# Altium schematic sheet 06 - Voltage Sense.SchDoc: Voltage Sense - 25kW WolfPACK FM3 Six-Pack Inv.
size 431 x 279 mm; Date: 09/2024; DocumentNumber: CRD25DA12N-FMC; Revision: 2.0; SheetNumber: 6; SheetTotal: 9; SheetSize: B
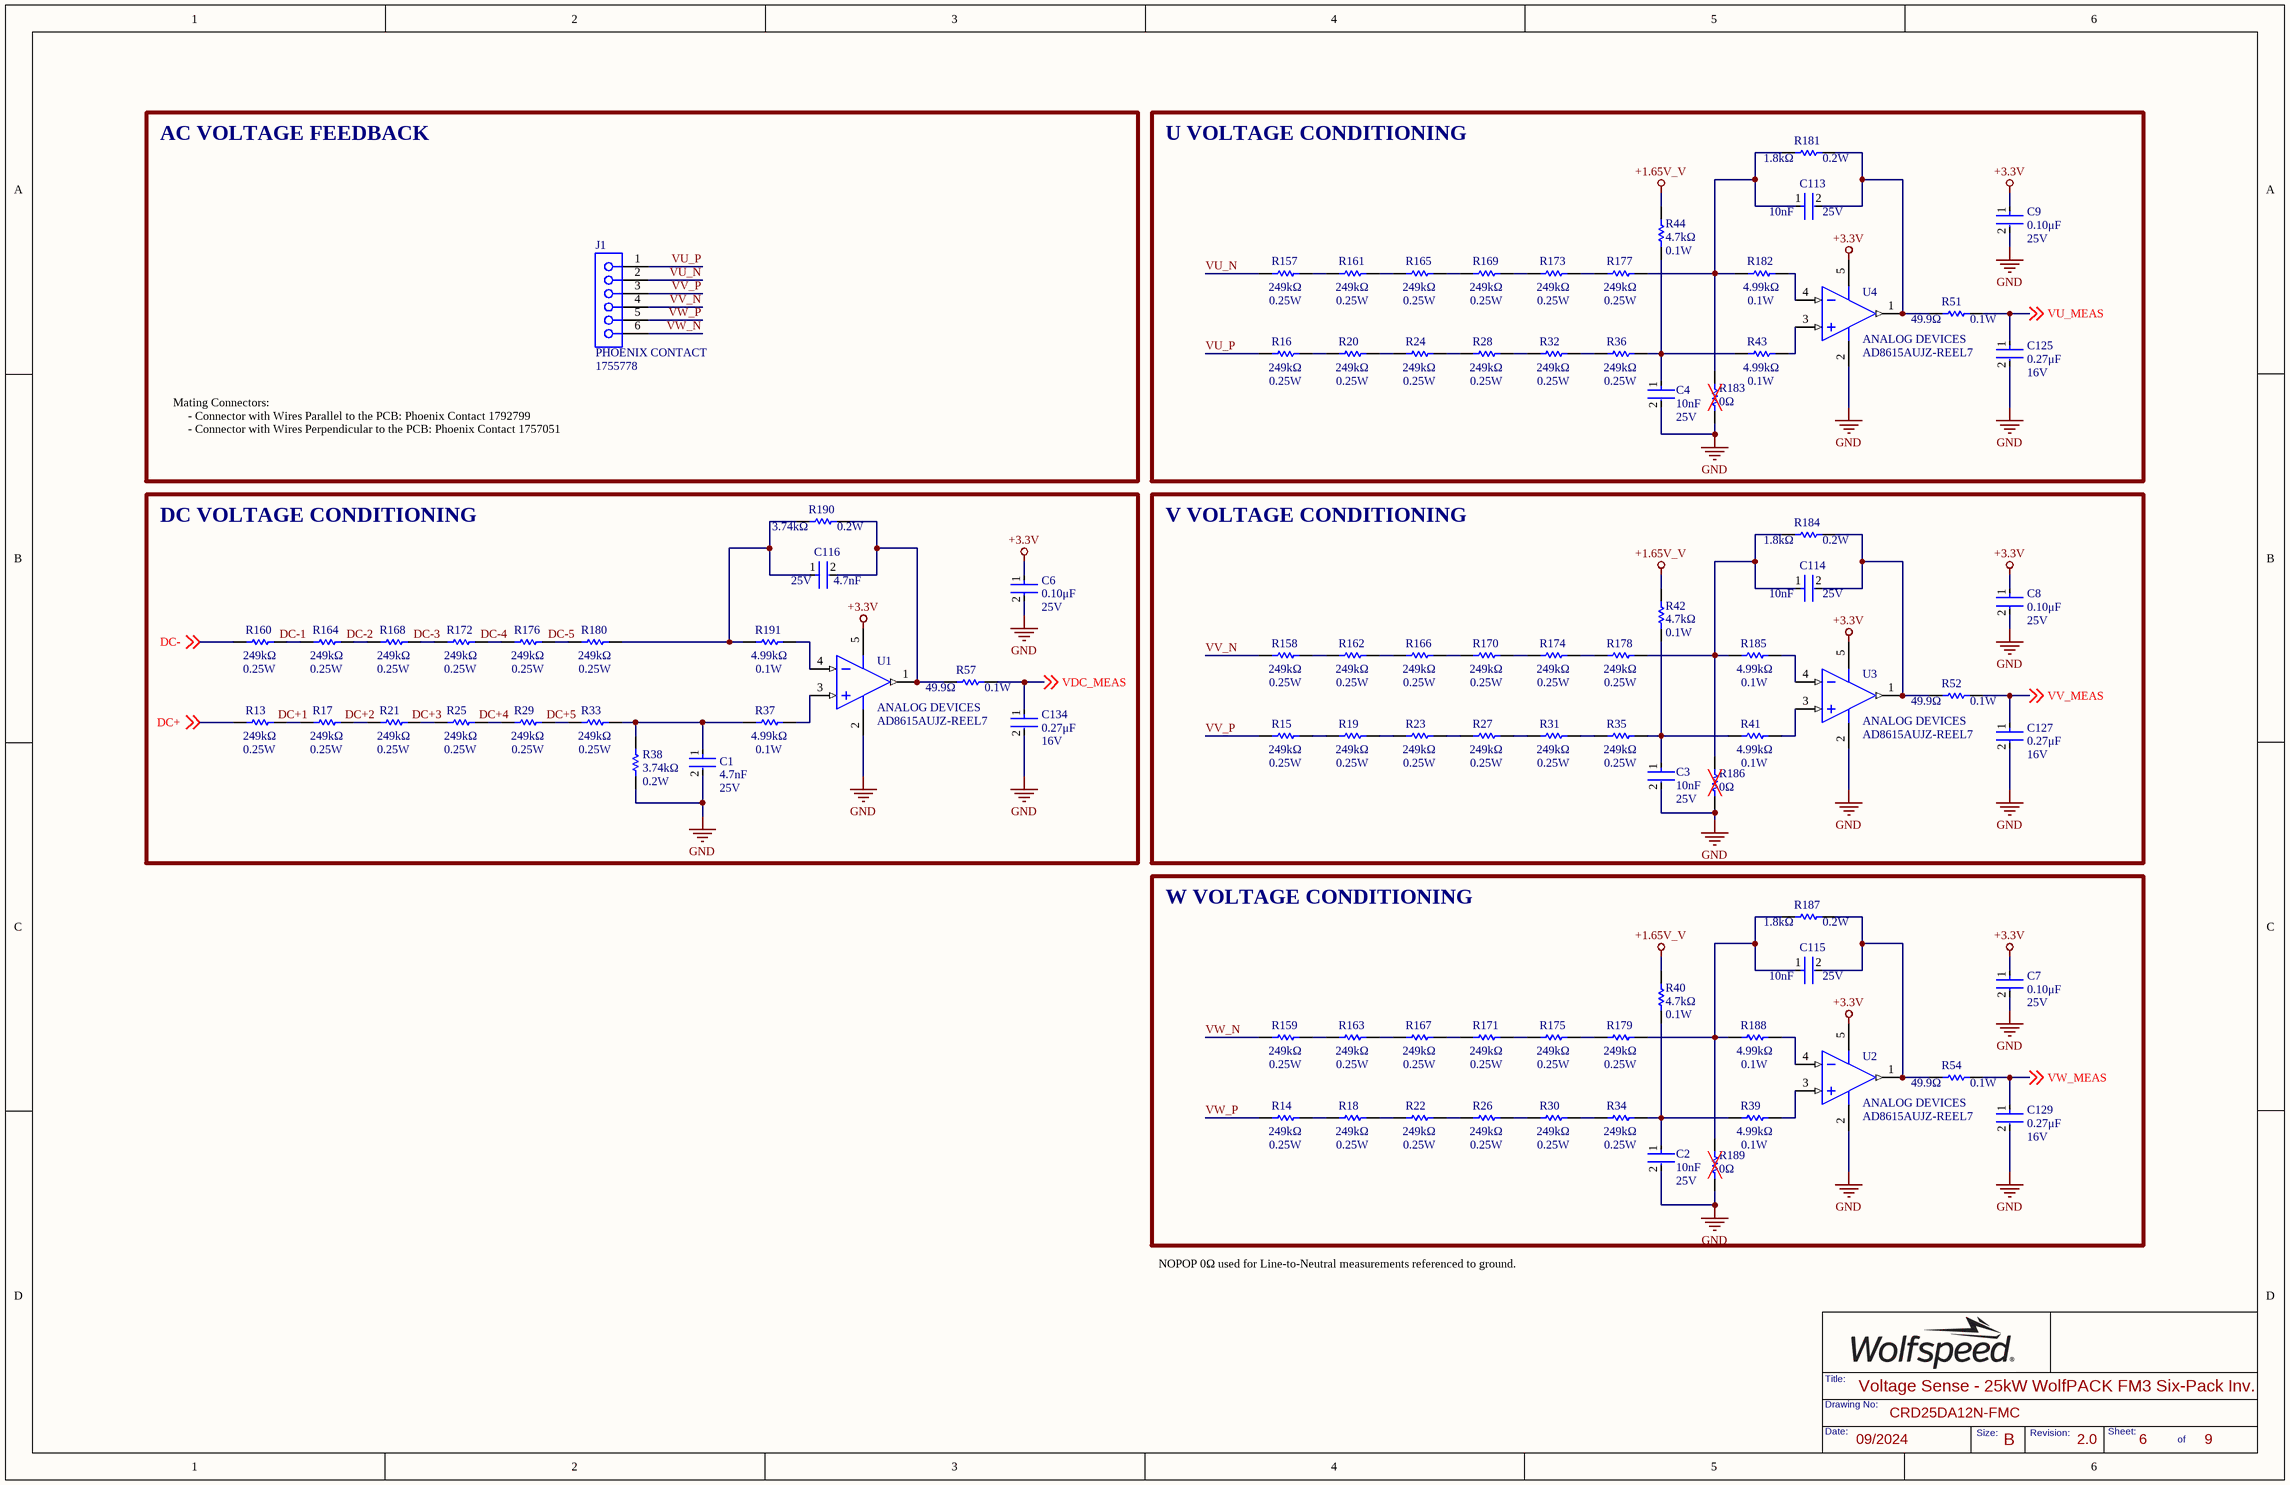
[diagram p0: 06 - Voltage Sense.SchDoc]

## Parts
C1  Voltage Rating: 25V  Capacitance: 4.7nF  [FP-C0603C-CF-IPC_B]  (hidden comment: C0603C472K3RAC7867)
C2  value 10nF  Voltage Rating: 25V  [FP-C0603C-CF-IPC_B]  (hidden comment: CL10B103KA8WPNC)
C3  value 10nF  Voltage Rating: 25V  [FP-C0603C-CF-IPC_B]  (hidden comment: CL10B103KA8WPNC)
C4  value 10nF  Voltage Rating: 25V  [FP-C0603C-CF-IPC_B]  (hidden comment: CL10B103KA8WPNC)
C6  Voltage Rating: 25V  Capacitance: 0.10μF  [FP-C0603C-CF-IPC_B]  (hidden comment: C0603C104K3RACTU)
C7  Voltage Rating: 25V  Capacitance: 0.10μF  [FP-C0603C-CF-IPC_B]  (hidden comment: C0603C104K3RACTU)
C8  Voltage Rating: 25V  Capacitance: 0.10μF  [FP-C0603C-CF-IPC_B]  (hidden comment: C0603C104K3RACTU)
C9  Voltage Rating: 25V  Capacitance: 0.10μF  [FP-C0603C-CF-IPC_B]  (hidden comment: C0603C104K3RACTU)
C113  value 10nF  Voltage Rating: 25V  [FP-C0603C-CF-IPC_B]  (hidden comment: CL10B103KA8WPNC)
C114  value 10nF  Voltage Rating: 25V  [FP-C0603C-CF-IPC_B]  (hidden comment: CL10B103KA8WPNC)
C115  value 10nF  Voltage Rating: 25V  [FP-C0603C-CF-IPC_B]  (hidden comment: CL10B103KA8WPNC)
C116  Voltage Rating: 25V  Capacitance: 4.7nF  [FP-C0603C-CF-IPC_B]  (hidden comment: C0603C472K3RAC7867)
C125  Voltage Rating (DC): 16V  Capacitance: 0.27μF  [FP-GCM188-0_1-IPC_A]  (hidden comment: GCM188R71C274KA37D)
C127  Voltage Rating (DC): 16V  Capacitance: 0.27μF  [FP-GCM188-0_1-IPC_A]  (hidden comment: GCM188R71C274KA37D)
C129  Voltage Rating (DC): 16V  Capacitance: 0.27μF  [FP-GCM188-0_1-IPC_A]  (hidden comment: GCM188R71C274KA37D)
C134  Voltage Rating (DC): 16V  Capacitance: 0.27μF  [FP-GCM188-0_1-IPC_A]  (hidden comment: GCM188R71C274KA37D)
J1  1755778  Manufacturer Print: PHOENIX CONTACT  [1755778]
R13  Resistance: 249kΩ  Power: 0.25W  [RESC3216X65X50NL15T25]  (hidden comment: TNPW1206249KBEEA)
R14  Resistance: 249kΩ  Power: 0.25W  [RESC3216X65X50NL15T25]  (hidden comment: TNPW1206249KBEEA)
R15  Resistance: 249kΩ  Power: 0.25W  [RESC3216X65X50NL15T25]  (hidden comment: TNPW1206249KBEEA)
R16  Resistance: 249kΩ  Power: 0.25W  [RESC3216X65X50NL15T25]  (hidden comment: TNPW1206249KBEEA)
R17  Resistance: 249kΩ  Power: 0.25W  [RESC3216X65X50NL15T25]  (hidden comment: TNPW1206249KBEEA)
R18  Resistance: 249kΩ  Power: 0.25W  [RESC3216X65X50NL15T25]  (hidden comment: TNPW1206249KBEEA)
R19  Resistance: 249kΩ  Power: 0.25W  [RESC3216X65X50NL15T25]  (hidden comment: TNPW1206249KBEEA)
R20  Resistance: 249kΩ  Power: 0.25W  [RESC3216X65X50NL15T25]  (hidden comment: TNPW1206249KBEEA)
R21  Resistance: 249kΩ  Power: 0.25W  [RESC3216X65X50NL15T25]  (hidden comment: TNPW1206249KBEEA)
R22  Resistance: 249kΩ  Power: 0.25W  [RESC3216X65X50NL15T25]  (hidden comment: TNPW1206249KBEEA)
R23  Resistance: 249kΩ  Power: 0.25W  [RESC3216X65X50NL15T25]  (hidden comment: TNPW1206249KBEEA)
R24  Resistance: 249kΩ  Power: 0.25W  [RESC3216X65X50NL15T25]  (hidden comment: TNPW1206249KBEEA)
R25  Resistance: 249kΩ  Power: 0.25W  [RESC3216X65X50NL15T25]  (hidden comment: TNPW1206249KBEEA)
R26  Resistance: 249kΩ  Power: 0.25W  [RESC3216X65X50NL15T25]  (hidden comment: TNPW1206249KBEEA)
R27  Resistance: 249kΩ  Power: 0.25W  [RESC3216X65X50NL15T25]  (hidden comment: TNPW1206249KBEEA)
R28  Resistance: 249kΩ  Power: 0.25W  [RESC3216X65X50NL15T25]  (hidden comment: TNPW1206249KBEEA)
R29  Resistance: 249kΩ  Power: 0.25W  [RESC3216X65X50NL15T25]  (hidden comment: TNPW1206249KBEEA)
R30  Resistance: 249kΩ  Power: 0.25W  [RESC3216X65X50NL15T25]  (hidden comment: TNPW1206249KBEEA)
R31  Resistance: 249kΩ  Power: 0.25W  [RESC3216X65X50NL15T25]  (hidden comment: TNPW1206249KBEEA)
R32  Resistance: 249kΩ  Power: 0.25W  [RESC3216X65X50NL15T25]  (hidden comment: TNPW1206249KBEEA)
R33  Resistance: 249kΩ  Power: 0.25W  [RESC3216X65X50NL15T25]  (hidden comment: TNPW1206249KBEEA)
R34  Resistance: 249kΩ  Power: 0.25W  [RESC3216X65X50NL15T25]  (hidden comment: TNPW1206249KBEEA)
R35  Resistance: 249kΩ  Power: 0.25W  [RESC3216X65X50NL15T25]  (hidden comment: TNPW1206249KBEEA)
R36  Resistance: 249kΩ  Power: 0.25W  [RESC3216X65X50NL15T25]  (hidden comment: TNPW1206249KBEEA)
R37  Power Rating: 0.1W  Resistance: 4.99kΩ  [FP-MCR03-IPC_B]  (hidden comment: RC0603FR-074K99L)
R38  Max Power Dissipation: 0.2W  Resistance: 3.74kΩ  [FP-MCR03-IPC_B]  (hidden comment: ERJ-PB3B3741V)
R39  Power Rating: 0.1W  Resistance: 4.99kΩ  [FP-MCR03-IPC_B]  (hidden comment: RC0603FR-074K99L)
R40  Resistance: 4.7kΩ  Power Rating: 0.1W  [FP-MCR03-IPC_B]  (hidden comment: CRCW06034K70FKTA)
R41  Power Rating: 0.1W  Resistance: 4.99kΩ  [FP-MCR03-IPC_B]  (hidden comment: RC0603FR-074K99L)
R42  Resistance: 4.7kΩ  Power Rating: 0.1W  [FP-MCR03-IPC_B]  (hidden comment: CRCW06034K70FKTA)
R43  Power Rating: 0.1W  Resistance: 4.99kΩ  [FP-MCR03-IPC_B]  (hidden comment: RC0603FR-074K99L)
R44  Resistance: 4.7kΩ  Power Rating: 0.1W  [FP-MCR03-IPC_B]  (hidden comment: CRCW06034K70FKTA)
R51  Resistance: 49.9Ω  Power Rating: 0.1W  [FP-MCR03-IPC_B]  (hidden comment: ERJ-3EKF49R9V)
R52  Resistance: 49.9Ω  Power Rating: 0.1W  [FP-MCR03-IPC_B]  (hidden comment: ERJ-3EKF49R9V)
R54  Resistance: 49.9Ω  Power Rating: 0.1W  [FP-MCR03-IPC_B]  (hidden comment: ERJ-3EKF49R9V)
R57  Resistance: 49.9Ω  Power Rating: 0.1W  [FP-MCR03-IPC_B]  (hidden comment: ERJ-3EKF49R9V)
R157  Resistance: 249kΩ  Power: 0.25W  [RESC3216X65X50NL15T25]  (hidden comment: TNPW1206249KBEEA)
R158  Resistance: 249kΩ  Power: 0.25W  [RESC3216X65X50NL15T25]  (hidden comment: TNPW1206249KBEEA)
R159  Resistance: 249kΩ  Power: 0.25W  [RESC3216X65X50NL15T25]  (hidden comment: TNPW1206249KBEEA)
R160  Resistance: 249kΩ  Power: 0.25W  [RESC3216X65X50NL15T25]  (hidden comment: TNPW1206249KBEEA)
R161  Resistance: 249kΩ  Power: 0.25W  [RESC3216X65X50NL15T25]  (hidden comment: TNPW1206249KBEEA)
R162  Resistance: 249kΩ  Power: 0.25W  [RESC3216X65X50NL15T25]  (hidden comment: TNPW1206249KBEEA)
R163  Resistance: 249kΩ  Power: 0.25W  [RESC3216X65X50NL15T25]  (hidden comment: TNPW1206249KBEEA)
R164  Resistance: 249kΩ  Power: 0.25W  [RESC3216X65X50NL15T25]  (hidden comment: TNPW1206249KBEEA)
R165  Resistance: 249kΩ  Power: 0.25W  [RESC3216X65X50NL15T25]  (hidden comment: TNPW1206249KBEEA)
R166  Resistance: 249kΩ  Power: 0.25W  [RESC3216X65X50NL15T25]  (hidden comment: TNPW1206249KBEEA)
R167  Resistance: 249kΩ  Power: 0.25W  [RESC3216X65X50NL15T25]  (hidden comment: TNPW1206249KBEEA)
R168  Resistance: 249kΩ  Power: 0.25W  [RESC3216X65X50NL15T25]  (hidden comment: TNPW1206249KBEEA)
R169  Resistance: 249kΩ  Power: 0.25W  [RESC3216X65X50NL15T25]  (hidden comment: TNPW1206249KBEEA)
R170  Resistance: 249kΩ  Power: 0.25W  [RESC3216X65X50NL15T25]  (hidden comment: TNPW1206249KBEEA)
R171  Resistance: 249kΩ  Power: 0.25W  [RESC3216X65X50NL15T25]  (hidden comment: TNPW1206249KBEEA)
R172  Resistance: 249kΩ  Power: 0.25W  [RESC3216X65X50NL15T25]  (hidden comment: TNPW1206249KBEEA)
R173  Resistance: 249kΩ  Power: 0.25W  [RESC3216X65X50NL15T25]  (hidden comment: TNPW1206249KBEEA)
R174  Resistance: 249kΩ  Power: 0.25W  [RESC3216X65X50NL15T25]  (hidden comment: TNPW1206249KBEEA)
R175  Resistance: 249kΩ  Power: 0.25W  [RESC3216X65X50NL15T25]  (hidden comment: TNPW1206249KBEEA)
R176  Resistance: 249kΩ  Power: 0.25W  [RESC3216X65X50NL15T25]  (hidden comment: TNPW1206249KBEEA)
R177  Resistance: 249kΩ  Power: 0.25W  [RESC3216X65X50NL15T25]  (hidden comment: TNPW1206249KBEEA)
R178  Resistance: 249kΩ  Power: 0.25W  [RESC3216X65X50NL15T25]  (hidden comment: TNPW1206249KBEEA)
R179  Resistance: 249kΩ  Power: 0.25W  [RESC3216X65X50NL15T25]  (hidden comment: TNPW1206249KBEEA)
R180  Resistance: 249kΩ  Power: 0.25W  [RESC3216X65X50NL15T25]  (hidden comment: TNPW1206249KBEEA)
R181  Resistance: 1.8kΩ  Max Power Dissipation: 0.2W  [FP-MCR03-IPC_B]  (hidden comment: ERJ-PB3B1801V)
R182  Power Rating: 0.1W  Resistance: 4.99kΩ  [FP-MCR03-IPC_B]  (hidden comment: RC0603FR-074K99L)
R183  Resistance: 0Ω  [FP-MCR03-IPC_B]  (hidden comment: CRCW06030000Z0EB)
R184  Resistance: 1.8kΩ  Max Power Dissipation: 0.2W  [FP-MCR03-IPC_B]  (hidden comment: ERJ-PB3B1801V)
R185  Power Rating: 0.1W  Resistance: 4.99kΩ  [FP-MCR03-IPC_B]  (hidden comment: RC0603FR-074K99L)
R186  Resistance: 0Ω  [FP-MCR03-IPC_B]  (hidden comment: CRCW06030000Z0EB)
R187  Resistance: 1.8kΩ  Max Power Dissipation: 0.2W  [FP-MCR03-IPC_B]  (hidden comment: ERJ-PB3B1801V)
R188  Power Rating: 0.1W  Resistance: 4.99kΩ  [FP-MCR03-IPC_B]  (hidden comment: RC0603FR-074K99L)
R189  Resistance: 0Ω  [FP-MCR03-IPC_B]  (hidden comment: CRCW06030000Z0EB)
R190  Max Power Dissipation: 0.2W  Resistance: 3.74kΩ  [FP-MCR03-IPC_B]  (hidden comment: ERJ-PB3B3741V)
R191  Power Rating: 0.1W  Resistance: 4.99kΩ  [FP-MCR03-IPC_B]  (hidden comment: RC0603FR-074K99L)
U1  Manufacturer: ANALOG DEVICES  [ADI-UJ-5_M]  (hidden comment: AD8615AUJZ-REEL7)
U2  Manufacturer: ANALOG DEVICES  [ADI-UJ-5_M]  (hidden comment: AD8615AUJZ-REEL7)
U3  Manufacturer: ANALOG DEVICES  [ADI-UJ-5_M]  (hidden comment: AD8615AUJZ-REEL7)
U4  Manufacturer: ANALOG DEVICES  [ADI-UJ-5_M]  (hidden comment: AD8615AUJZ-REEL7)

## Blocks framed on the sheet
AC VOLTAGE FEEDBACK: J1
U VOLTAGE CONDITIONING: C4 C9 C113 C125 R16 R20 R24 R28 R32 R36 R43 R44 R51 R157 R161 R165 R169 R173 R177 R181-R183 U4
DC VOLTAGE CONDITIONING: C1 C6 C116 C134 R13 R17 R21 R25 R29 R33 R37 R38 R57 R160 R164 R168 R172 R176 R180 R190 R191 U1
V VOLTAGE CONDITIONING: C3 C8 C114 C127 R15 R19 R23 R27 R31 R35 R41 R42 R52 R158 R162 R166 R170 R174 R178 R184-R186 U3
W VOLTAGE CONDITIONING: C2 C7 C115 C129 R14 R18 R22 R26 R30 R34 R39 R40 R54 R159 R163 R167 R171 R175 R179 R187-R189 U2

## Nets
+1.65V_V: R40.2 R42.2 R44.2
+3.3V: C6.1 C7.1 C8.1 C9.1 U1.5(+V) U2.5(+V) U3.5(+V) U4.5(+V)
GND: C1.2 C2.2 C3.2 C4.2 C6.2 C7.2 C8.2 C9.2 C125.2 C127.2 C129.2 C134.2 R38.1 R183.1 R186.1 R189.1 U1.2(-V) U2.2(-V) U3.2(-V) U4.2(-V)
DC+: R13.1 ; off-sheet DC+
DC+1: R13.2 R17.1
DC+2: R17.2 R21.1
DC+3: R21.2 R25.1
DC+4: R25.2 R29.1
DC+5: R29.2 R33.1
DC-: R160.1 ; off-sheet DC-
DC-1: R160.2 R164.1
DC-2: R164.2 R168.1
DC-3: R168.2 R172.1
DC-4: R172.2 R176.1
DC-5: R176.2 R180.1
VDC_MEAS: C134.1 R57.2 ; off-sheet VDC_MEAS
VU_MEAS: C125.1 R51.2 ; off-sheet VU_MEAS
VU_N: J1.2 R157.1
VU_P: J1.1 R16.1
VV_MEAS: C127.1 R52.2 ; off-sheet VV_MEAS
VV_N: J1.4 R158.1
VV_P: J1.3 R15.1
VW_MEAS: C129.1 R54.2 ; off-sheet VW_MEAS
VW_N: J1.6 R159.1
VW_P: J1.5 R14.1
NetC1_1: C1.1 R33.2 R37.1 R38.2
NetC2_1: C2.1 R34.2 R39.1 R40.1
NetC3_1: C3.1 R35.2 R41.1 R42.1
NetC4_1: C4.1 R36.2 R43.1 R44.1
NetC113_1: C113.1 R177.2 R181.2 R182.1 R183.2
NetC113_2: C113.2 R51.1 R181.1 U4.1(OUT)
NetC114_1: C114.1 R178.2 R184.2 R185.1 R186.2
NetC114_2: C114.2 R52.1 R184.1 U3.1(OUT)
NetC115_1: C115.1 R179.2 R187.2 R188.1 R189.2
NetC115_2: C115.2 R54.1 R187.1 U2.1(OUT)
NetC116_1: C116.1 R180.2 R190.1 R191.1
NetC116_2: C116.2 R57.1 R190.2 U1.1(OUT)
NetR14_2: R14.2 R18.1
NetR15_2: R15.2 R19.1
NetR16_2: R16.2 R20.1
NetR18_2: R18.2 R22.1
NetR19_2: R19.2 R23.1
NetR20_2: R20.2 R24.1
NetR22_2: R22.2 R26.1
NetR23_2: R23.2 R27.1
NetR24_2: R24.2 R28.1
NetR26_2: R26.2 R30.1
NetR27_2: R27.2 R31.1
NetR28_2: R28.2 R32.1
NetR30_2: R30.2 R34.1
NetR31_2: R31.2 R35.1
NetR32_2: R32.2 R36.1
NetR37_2: R37.2 U1.3(+IN)
NetR39_2: R39.2 U2.3(+IN)
NetR41_2: R41.2 U3.3(+IN)
NetR43_2: R43.2 U4.3(+IN)
NetR157_2: R157.2 R161.1
NetR158_2: R158.2 R162.1
NetR159_2: R159.2 R163.1
NetR161_2: R161.2 R165.1
NetR162_2: R162.2 R166.1
NetR163_2: R163.2 R167.1
NetR165_2: R165.2 R169.1
NetR166_2: R166.2 R170.1
NetR167_2: R167.2 R171.1
NetR169_2: R169.2 R173.1
NetR170_2: R170.2 R174.1
NetR171_2: R171.2 R175.1
NetR173_2: R173.2 R177.1
NetR174_2: R174.2 R178.1
NetR175_2: R175.2 R179.1
NetR182_2: R182.2 U4.4(-IN)
NetR185_2: R185.2 U3.4(-IN)
NetR188_2: R188.2 U2.4(-IN)
NetR191_2: R191.2 U1.4(-IN)

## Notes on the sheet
- Mating Connectors:
  - Connector with Wires Parallel to the PCB: Phoenix Contact 1792799
  - Connector with Wires Perpendicular to the PCB: Phoenix Contact 1757051
- NOPOP 0Ω used for Line-to-Neutral measurements referenced to ground.

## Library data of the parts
C1 C116 = C0603C472K3RAC7867: CAP CER 4700PF 25V 10% X7R 0603; Manufacturer: KEMET; Manufacturer Part Number: C0603C472K3RACTU; Dielectric Material: Ceramic; Value: 4.7nF
C2-C4 C113-C115 = CL10B103KA8WPNC: CAP CER 10000PF 25V X7R 0603; Manufacturer: SAMSUNG; Tolerance: 10%
C6-C9 = CMP-2006-03057-2: CAP CER 0.1UF 25V X7R 0603; Manufacturer: KEMET; Value: 0.10μF; Material: Ceramic; Tolerance: 0.1; Temperature Coefficient: 30ppm/°C; Automotive Grade: Grade 1
C125 C127 C129 C134 = CMP-06035-043171-1: CAP CER 0.27UF 16V X7R 0603; Manufacturer: MURATA; Tolerance: 10%; Value: 0.27μF
J1 = 1755778: TERM BLOCK HDR 6POS VERT 5.08MM; Voltage Rating: 250V; Current Rating: 12A; Number of Positions: 6; Number of Levels: 1; Voltage: 300V; Gender: Male; Connector Type: Plug; Approvals: UL,CSA,VDE,cULus,CB,EAC
R13-R36 R157-R180 = CMP-2003-04604-1: RES 249K OHM 0.1% 1/4W 1206; Manufacturer: VISHAY DALE; Value: 249kΩ
R37 R39 R41 R43 R182 R185 R188 R191 = RC0603FR-074K99L: RES 4.99K OHM 1% 1/10W 0603; Manufacturer: YAGEO; Voltage Rating: 75V; Temperature Coefficient: 100ppm/°C; Voltage Rating (DC): 50V; Value: 4.99kΩ
R38 R190 = ERJ-PB3B3741V: RES SMD 3.74K OHM 0.1% 1/5W 0603; Manufacturer: PANASONIC; Temperature Coefficient: 50ppm/°C; Value: 3.74kΩ
R40 R42 R44 = CRCW06034K70FKTA: RES SMD 4.7K OHM 1% 1/10W 0603; Manufacturer: VISHAY DALE; Voltage Rating: 75V; Max Power Dissipation: 100mW; Temperature Coefficient: 100ppm/°C; Value: 4.7kΩ
R51 R52 R54 R57 = ERJ-3EKF49R9V: RES SMD 49.9 OHM 1% 1/10W 0603; Manufacturer: PANASONIC; Temperature Coefficient: 100ppm/°C; Voltage Rating: 75V; Max Power Dissipation: 100mW; Voltage Rating (DC): 50V; Working Voltage: 6V; Value: 49.9Ω
R181 R184 R187 = ERJ-PB3B1801V: RES SMD 1.8K OHM 0.1% 1/5W 0603; Manufacturer: PANASONIC; Temperature Coefficient: 50ppm/°C; Value: 1.8kΩ
R183 R186 R189 = CRCW06030000Z0EB: RES SMD 0 OHM JUMPER 1/10W 0603; Manufacturer: VISHAY DALE; Manufacturer Part Number: CRCW06030000Z0EBC; Max Power Dissipation: 100mW; Voltage Rating: 75V; Tolerance: 1%; Temperature Coefficient: 100ppm/°C; Value: 0Ω
U1-U4 = CMP-0384-02059-2: IC OPAMP GP 1 CIRCUIT TSOT23-5; Generic Part Number: AD8615; Iq/Amp: 1.7mA; V Span Max: 6V; Amplifiers Per Package: 1; Small Signal Bandwidth: 23MHz; Input Offset Voltage: 80uV; V Span Min: 2.7V; Slew Rate: 12V/us; Input Bias Current: 200fA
